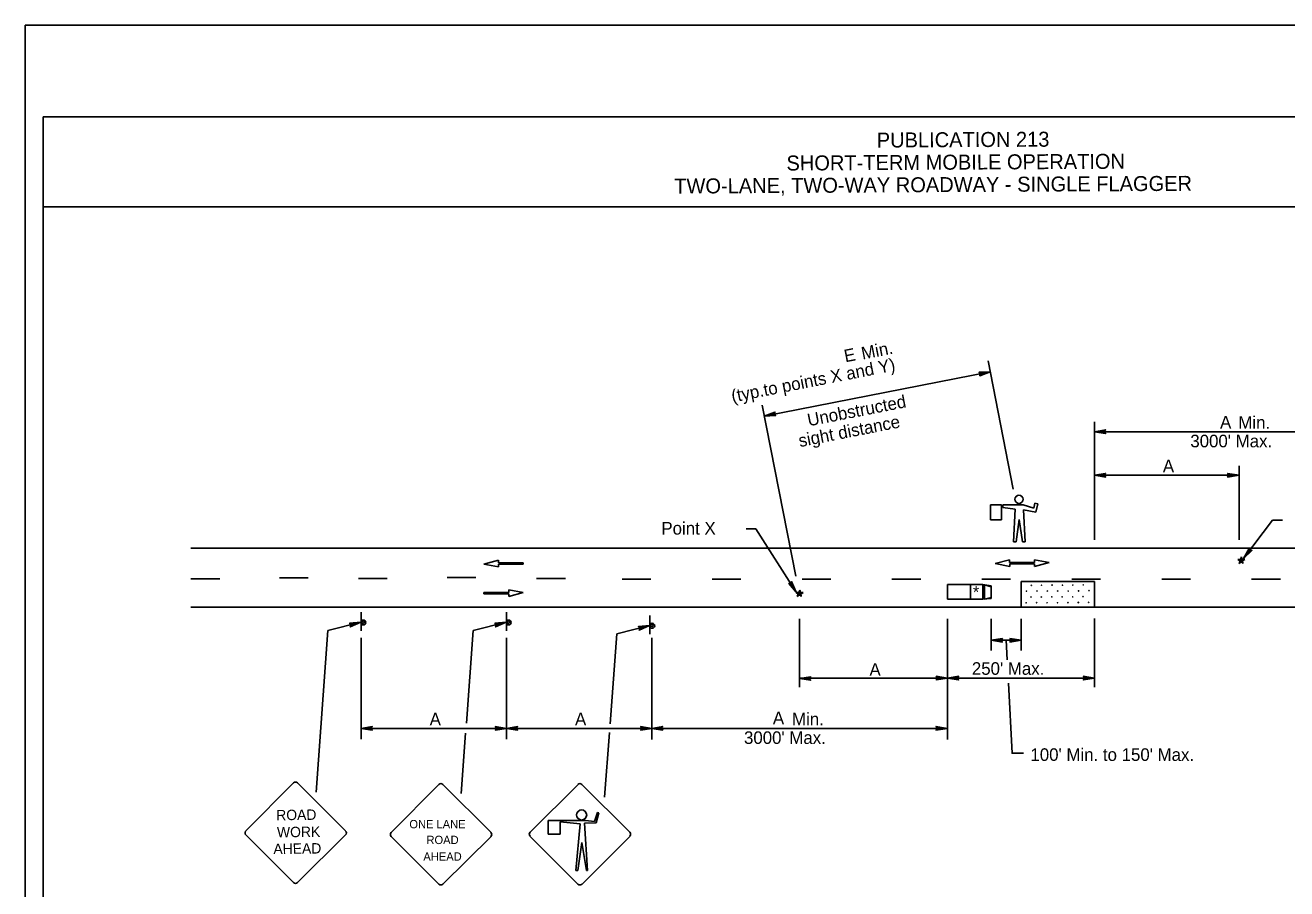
# Model space of a CAD drawing. Extents: x -14145 to -13662, y 30244 to 30661.
# Drawn here: x -13892.17 to -13871.13, y 30462.9 to 30477.31 of the extents above; entities that cross this region are included whole.
import ezdxf

# ---------------------------------------------------------------- set-up
doc = ezdxf.new("R2010")
doc.units = 0
for name, color, linetype in [('1', 7, 'Continuous'), ('10', 7, 'Continuous'), ('2', 7, 'Continuous'), ('4', 7, 'Continuous'), ('61', 7, 'Continuous')]:
    doc.layers.add(name, color=color, linetype=linetype)

msp = doc.modelspace()

# ---------------------------------------------------------------- linework, layer by layer
at = {"layer": '1'}
for p, q in [((-13875.693, 30469.57), (-13876.111, 30471.707)), ((-13876.076, 30471.528), (-13879.846, 30470.789)), ((-13879.322, 30468.116), (-13879.881, 30470.969)), ((-13874.338, 30468.722), (-13874.338, 30470.692)), ((-13869.454, 30470.527), (-13874.338, 30470.527)), ((-13871.926, 30468.722), (-13871.926, 30469.959)), ((-13871.926, 30469.802), (-13874.338, 30469.802)), ((-13875.887, 30469.306), (-13876.075, 30469.306)), ((-13876.075, 30469.306), (-13876.075, 30469.056)), ((-13875.887, 30469.056), (-13875.887, 30469.306)), ((-13875.529, 30469.306), (-13875.869, 30469.306)), ((-13875.869, 30469.306), (-13875.869, 30469.262)), ((-13875.869, 30469.262), (-13875.663, 30469.236)), ((-13875.351, 30469.254), (-13875.529, 30469.306)), ((-13875.333, 30469.334), (-13875.351, 30469.254)), ((-13875.285, 30469.322), (-13875.333, 30469.334)), ((-13875.315, 30469.188), (-13875.285, 30469.322)), ((-13876.075, 30469.056), (-13875.887, 30469.056)), ((-13875.663, 30469.236), (-13875.691, 30468.69)), ((-13875.646, 30468.69), (-13875.592, 30469.064)), ((-13875.592, 30469.064), (-13875.539, 30468.69)), ((-13875.494, 30468.69), (-13875.52, 30469.226)), ((-13875.52, 30469.226), (-13875.315, 30469.188)), ((-13871.85, 30468.415), (-13871.367, 30469.053)), ((-13871.202, 30469.053), (-13871.367, 30469.053)), ((-13880.15, 30468.91), (-13879.985, 30468.91)), ((-13879.315, 30467.854), (-13879.984, 30468.91)), ((-13875.691, 30468.69), (-13875.646, 30468.69)), ((-13875.539, 30468.69), (-13875.494, 30468.69)), ((-13889.41, 30468.586), (-13863.13, 30468.586)), ((-13884.281, 30468.384), (-13884.523, 30468.318)), ((-13884.523, 30468.318), (-13884.279, 30468.272)), ((-13884.281, 30468.339), (-13884.281, 30468.384)), ((-13883.865, 30468.339), (-13884.281, 30468.339)), ((-13884.279, 30468.272), (-13884.279, 30468.317)), ((-13884.279, 30468.317), (-13883.865, 30468.317)), ((-13883.865, 30468.317), (-13883.865, 30468.339)), ((-13875.753, 30468.393), (-13875.994, 30468.327)), ((-13875.994, 30468.327), (-13875.75, 30468.281)), ((-13875.753, 30468.348), (-13875.753, 30468.393)), ((-13875.339, 30468.348), (-13875.753, 30468.348)), ((-13875.75, 30468.326), (-13875.336, 30468.326)), ((-13875.75, 30468.281), (-13875.75, 30468.326)), ((-13875.095, 30468.347), (-13875.339, 30468.393)), ((-13875.339, 30468.393), (-13875.339, 30468.348)), ((-13875.336, 30468.281), (-13875.095, 30468.347)), ((-13875.336, 30468.326), (-13875.336, 30468.281)), ((-13871.915, 30468.372), (-13871.927, 30468.33)), ((-13888.93, 30468.076), (-13889.41, 30468.076)), ((-13887.454, 30468.088), (-13887.934, 30468.088)), ((-13886.134, 30468.082), (-13886.614, 30468.082)), ((-13884.658, 30468.094), (-13885.138, 30468.094)), ((-13883.164, 30468.082), (-13883.644, 30468.082)), ((-13881.736, 30468.07), (-13882.216, 30468.07)), ((-13880.236, 30468.07), (-13880.716, 30468.07)), ((-13878.736, 30468.07), (-13879.216, 30468.07)), ((-13877.236, 30468.07), (-13877.716, 30468.07)), ((-13876.792, 30467.734), (-13876.792, 30467.98)), ((-13876.198, 30467.98), (-13876.792, 30467.98)), ((-13876.408, 30467.734), (-13876.408, 30467.98)), ((-13875.736, 30468.07), (-13876.216, 30468.07)), ((-13876.198, 30467.734), (-13876.198, 30467.98)), ((-13876.198, 30467.98), (-13876.06, 30467.956)), ((-13874.338, 30468.028), (-13875.562, 30468.028)), ((-13875.562, 30467.602), (-13875.562, 30468.028)), ((-13874.236, 30468.07), (-13874.716, 30468.07)), ((-13874.338, 30467.602), (-13874.338, 30468.028)), ((-13872.736, 30468.07), (-13873.216, 30468.07)), ((-13871.236, 30468.07), (-13871.716, 30468.07)), ((-13884.109, 30467.848), (-13884.523, 30467.848)), ((-13884.523, 30467.848), (-13884.523, 30467.826)), ((-13884.523, 30467.826), (-13884.106, 30467.826)), ((-13883.865, 30467.847), (-13884.109, 30467.893)), ((-13884.109, 30467.893), (-13884.109, 30467.848)), ((-13884.106, 30467.781), (-13883.865, 30467.847)), ((-13884.106, 30467.826), (-13884.106, 30467.781)), ((-13879.283, 30467.82), (-13879.295, 30467.778)), ((-13876.174, 30467.974), (-13876.06, 30467.938)), ((-13876.174, 30467.734), (-13876.174, 30467.974)), ((-13876.06, 30467.746), (-13876.06, 30467.956)), ((-13889.41, 30467.602), (-13863.13, 30467.602)), ((-13876.198, 30467.734), (-13876.792, 30467.734)), ((-13876.198, 30467.734), (-13876.06, 30467.746)), ((-13876.174, 30467.734), (-13876.06, 30467.764)), ((-13887.125, 30467.21), (-13886.578, 30467.35)), ((-13886.572, 30467.517), (-13886.572, 30467.205)), ((-13884.701, 30467.21), (-13884.154, 30467.35)), ((-13884.148, 30467.517), (-13884.148, 30467.205)), ((-13881.754, 30467.463), (-13881.754, 30467.151)), ((-13881.754, 30467.463), (-13881.754, 30467.151)), ((-13879.258, 30466.268), (-13879.258, 30467.408)), ((-13876.792, 30465.392), (-13876.792, 30467.408)), ((-13876.06, 30466.879), (-13876.06, 30467.408)), ((-13875.562, 30466.879), (-13875.562, 30467.408)), ((-13874.338, 30466.268), (-13874.338, 30467.414)), ((-13887.323, 30464.513), (-13887.125, 30467.21)), ((-13884.815, 30465.666), (-13884.701, 30467.211)), ((-13882.417, 30465.653), (-13882.307, 30467.157)), ((-13882.307, 30467.156), (-13881.76, 30467.296)), ((-13886.572, 30465.4), (-13886.572, 30467.088)), ((-13884.148, 30465.4), (-13884.148, 30467.088)), ((-13881.724, 30465.392), (-13881.724, 30467.088)), ((-13875.562, 30467.048), (-13876.06, 30467.048)), ((-13876.792, 30466.418), (-13879.258, 30466.418)), ((-13874.338, 30466.418), (-13876.792, 30466.418)), ((-13884.148, 30465.58), (-13886.572, 30465.58)), ((-13884.903, 30464.496), (-13884.829, 30465.502)), ((-13881.724, 30465.58), (-13884.148, 30465.58)), ((-13882.509, 30464.434), (-13882.43, 30465.511)), ((-13876.792, 30465.58), (-13881.724, 30465.58)), ((-13887.698, 30464.671), (-13888.493, 30463.868)), ((-13886.829, 30463.868), (-13887.632, 30464.671)), ((-13885.273, 30464.645), (-13886.068, 30463.842)), ((-13884.404, 30463.842), (-13885.207, 30464.645)), ((-13882.949, 30464.642), (-13883.752, 30463.847)), ((-13882.087, 30463.847), (-13882.889, 30464.642)), ((-13882.087, 30463.847), (-13882.889, 30464.642)), ((-13882.829, 30464.042), (-13883.452, 30464.042)), ((-13883.452, 30464.042), (-13883.452, 30463.817)), ((-13883.249, 30463.817), (-13883.249, 30464.019)), ((-13883.249, 30464.019), (-13882.919, 30463.989)), ((-13882.919, 30463.989), (-13882.987, 30463.209)), ((-13882.844, 30463.997), (-13882.649, 30464.004)), ((-13882.792, 30463.209), (-13882.844, 30463.997)), ((-13882.679, 30464.027), (-13882.829, 30464.042)), ((-13882.627, 30464.177), (-13882.679, 30464.027)), ((-13882.649, 30464.004), (-13882.604, 30464.169)), ((-13882.604, 30464.169), (-13882.627, 30464.177)), ((-13888.493, 30463.802), (-13887.698, 30463.007)), ((-13887.632, 30463.007), (-13886.829, 30463.802)), ((-13886.068, 30463.776), (-13885.273, 30462.981)), ((-13885.207, 30462.981), (-13884.404, 30463.776)), ((-13883.752, 30463.779), (-13882.949, 30462.977)), ((-13883.452, 30463.817), (-13883.249, 30463.817)), ((-13882.889, 30462.977), (-13882.087, 30463.779)), ((-13882.957, 30463.209), (-13882.889, 30463.674)), ((-13882.889, 30463.674), (-13882.814, 30463.209)), ((-13882.987, 30463.209), (-13882.957, 30463.209)), ((-13882.814, 30463.209), (-13882.792, 30463.209))]:
    msp.add_line(p, q, dxfattribs=at)
for points in [[(-13876.257, 30471.515), (-13876.249, 30471.505), (-13876.076, 30471.528), (-13876.257, 30471.515), (-13876.264, 30471.52), (-13876.076, 30471.528), (-13876.245, 30471.487), (-13876.249, 30471.474), (-13876.076, 30471.528), (-13876.252, 30471.461), (-13876.249, 30471.474)], [(-13879.664, 30470.802), (-13879.672, 30470.812), (-13879.845, 30470.789), (-13879.664, 30470.802), (-13879.657, 30470.797), (-13879.845, 30470.789), (-13879.676, 30470.83), (-13879.672, 30470.843), (-13879.845, 30470.789), (-13879.669, 30470.856), (-13879.672, 30470.843)], [(-13874.158, 30470.509), (-13874.164, 30470.521), (-13874.338, 30470.527), (-13874.158, 30470.509), (-13874.152, 30470.497), (-13874.338, 30470.527), (-13874.17, 30470.539), (-13874.164, 30470.551), (-13874.338, 30470.527), (-13874.152, 30470.557), (-13874.164, 30470.551)], [(-13874.158, 30469.784), (-13874.164, 30469.796), (-13874.338, 30469.802), (-13874.158, 30469.784), (-13874.152, 30469.772), (-13874.338, 30469.802), (-13874.17, 30469.814), (-13874.164, 30469.826), (-13874.338, 30469.802), (-13874.152, 30469.832), (-13874.164, 30469.826)], [(-13872.106, 30469.826), (-13872.1, 30469.814), (-13871.926, 30469.802), (-13872.106, 30469.826), (-13872.118, 30469.832), (-13871.926, 30469.802), (-13872.1, 30469.796), (-13872.106, 30469.784), (-13871.926, 30469.802), (-13872.118, 30469.772), (-13872.106, 30469.784)], [(-13871.726, 30468.546), (-13871.739, 30468.542), (-13871.85, 30468.415), (-13871.726, 30468.546), (-13871.713, 30468.549), (-13871.85, 30468.415), (-13871.753, 30468.559), (-13871.764, 30468.567), (-13871.85, 30468.415), (-13871.76, 30468.578), (-13871.764, 30468.567)], [(-13879.394, 30468.016), (-13879.395, 30468.003), (-13879.315, 30467.854), (-13879.394, 30468.016), (-13879.392, 30468.029), (-13879.315, 30467.854), (-13879.416, 30467.995), (-13879.427, 30467.988), (-13879.315, 30467.854), (-13879.436, 30467.996), (-13879.427, 30467.988)], [(-13886.758, 30467.326), (-13886.746, 30467.314), (-13886.578, 30467.35), (-13886.758, 30467.326), (-13886.764, 30467.332), (-13886.578, 30467.35), (-13886.74, 30467.296), (-13886.746, 30467.284), (-13886.578, 30467.35), (-13886.752, 30467.272), (-13886.746, 30467.284)], [(-13884.334, 30467.326), (-13884.322, 30467.314), (-13884.154, 30467.35), (-13884.334, 30467.326), (-13884.34, 30467.332), (-13884.154, 30467.35), (-13884.316, 30467.296), (-13884.322, 30467.284), (-13884.154, 30467.35), (-13884.328, 30467.272), (-13884.322, 30467.284)], [(-13881.94, 30467.272), (-13881.928, 30467.26), (-13881.76, 30467.296), (-13881.94, 30467.272), (-13881.946, 30467.278), (-13881.76, 30467.296), (-13881.922, 30467.242), (-13881.928, 30467.23), (-13881.76, 30467.296), (-13881.934, 30467.218), (-13881.928, 30467.23)], [(-13875.88, 30467.024), (-13875.886, 30467.036), (-13876.06, 30467.048), (-13875.88, 30467.024), (-13875.874, 30467.018), (-13876.06, 30467.048), (-13875.886, 30467.054), (-13875.88, 30467.066), (-13876.06, 30467.048), (-13875.874, 30467.078), (-13875.88, 30467.066)], [(-13875.794, 30466.723), (-13875.811, 30467.048)], [(-13875.742, 30467.072), (-13875.736, 30467.054), (-13875.562, 30467.048), (-13875.742, 30467.072), (-13875.748, 30467.078), (-13875.562, 30467.048), (-13875.736, 30467.042), (-13875.742, 30467.024), (-13875.562, 30467.048), (-13875.748, 30467.018), (-13875.742, 30467.024)], [(-13879.078, 30466.388), (-13879.084, 30466.4), (-13879.258, 30466.412), (-13879.078, 30466.388), (-13879.072, 30466.382), (-13879.258, 30466.412), (-13879.084, 30466.418), (-13879.078, 30466.43), (-13879.258, 30466.412), (-13879.072, 30466.442), (-13879.078, 30466.43)], [(-13876.972, 30466.442), (-13876.966, 30466.424), (-13876.792, 30466.418), (-13876.972, 30466.442), (-13876.978, 30466.448), (-13876.792, 30466.418), (-13876.966, 30466.412), (-13876.972, 30466.394), (-13876.792, 30466.418), (-13876.978, 30466.388), (-13876.972, 30466.394)], [(-13876.612, 30466.394), (-13876.618, 30466.406), (-13876.792, 30466.418), (-13876.612, 30466.394), (-13876.606, 30466.388), (-13876.792, 30466.418), (-13876.618, 30466.424), (-13876.612, 30466.436), (-13876.792, 30466.418), (-13876.606, 30466.448), (-13876.612, 30466.436)], [(-13875.52, 30465.164), (-13875.712, 30465.164), (-13875.774, 30466.336)], [(-13874.518, 30466.442), (-13874.512, 30466.424), (-13874.338, 30466.418), (-13874.518, 30466.442), (-13874.524, 30466.448), (-13874.338, 30466.418), (-13874.512, 30466.412), (-13874.518, 30466.394), (-13874.338, 30466.418), (-13874.524, 30466.388), (-13874.518, 30466.394)], [(-13886.392, 30465.562), (-13886.398, 30465.574), (-13886.572, 30465.58), (-13886.392, 30465.562), (-13886.386, 30465.55), (-13886.572, 30465.58), (-13886.398, 30465.592), (-13886.392, 30465.604), (-13886.572, 30465.58), (-13886.386, 30465.61), (-13886.392, 30465.604)], [(-13884.328, 30465.604), (-13884.316, 30465.586), (-13884.148, 30465.58), (-13884.328, 30465.604), (-13884.334, 30465.61), (-13884.148, 30465.58), (-13884.316, 30465.568), (-13884.328, 30465.556), (-13884.148, 30465.58), (-13884.334, 30465.55), (-13884.328, 30465.556)], [(-13883.968, 30465.562), (-13883.974, 30465.574), (-13884.148, 30465.58), (-13883.968, 30465.562), (-13883.962, 30465.55), (-13884.148, 30465.58), (-13883.974, 30465.592), (-13883.968, 30465.604), (-13884.148, 30465.58), (-13883.962, 30465.61), (-13883.968, 30465.604)], [(-13881.904, 30465.604), (-13881.892, 30465.586), (-13881.724, 30465.58), (-13881.904, 30465.604), (-13881.91, 30465.61), (-13881.724, 30465.58), (-13881.892, 30465.568), (-13881.904, 30465.556), (-13881.724, 30465.58), (-13881.91, 30465.55), (-13881.904, 30465.556)], [(-13881.544, 30465.562), (-13881.55, 30465.574), (-13881.724, 30465.58), (-13881.544, 30465.562), (-13881.538, 30465.55), (-13881.724, 30465.58), (-13881.556, 30465.592), (-13881.55, 30465.604), (-13881.724, 30465.58), (-13881.538, 30465.61), (-13881.55, 30465.604)], [(-13876.972, 30465.604), (-13876.966, 30465.592), (-13876.792, 30465.58), (-13876.972, 30465.604), (-13876.984, 30465.61), (-13876.792, 30465.58), (-13876.966, 30465.574), (-13876.972, 30465.562), (-13876.792, 30465.58), (-13876.984, 30465.55), (-13876.972, 30465.562)]]:
    msp.add_lwpolyline(points, dxfattribs=at)
for centre, radius in [((-13875.597, 30469.4), 0.0672), ((-13875.472, 30467.869), 0.00272), ((-13875.397, 30467.771), 0.00272), ((-13875.392, 30467.967), 0.00272), ((-13875.297, 30467.871), 0.00272), ((-13875.226, 30467.771), 0.00272), ((-13875.219, 30467.968), 0.00272), ((-13875.125, 30467.869), 0.00272), ((-13875.049, 30467.772), 0.00272), ((-13875.045, 30467.969), 0.00272), ((-13874.95, 30467.871), 0.00272), ((-13874.876, 30467.772), 0.00272), ((-13874.871, 30467.968), 0.00272), ((-13874.776, 30467.87), 0.00272), ((-13874.701, 30467.773), 0.00272), ((-13874.699, 30467.97), 0.00272), ((-13874.604, 30467.875), 0.00272), ((-13874.602, 30467.872), 0.00272), ((-13874.53, 30467.777), 0.00272), ((-13874.524, 30467.973), 0.00272), ((-13874.429, 30467.877), 0.00272), ((-13875.477, 30467.674), 0.00272), ((-13875.302, 30467.675), 0.00272), ((-13875.129, 30467.674), 0.00272), ((-13874.955, 30467.676), 0.00272), ((-13874.781, 30467.677), 0.00272), ((-13874.609, 30467.68), 0.00272), ((-13874.608, 30467.677), 0.00272), ((-13874.435, 30467.681), 0.00272), ((-13886.533, 30467.345), 0.0408), ((-13884.109, 30467.345), 0.0408), ((-13881.715, 30467.291), 0.0408), ((-13882.892, 30464.135), 0.0844)]:
    msp.add_circle(centre, radius, dxfattribs=at)
for centre, radius, start, end in [((-13886.538, 30467.353), 0.0214, 189.521, 184.2501), ((-13884.114, 30467.353), 0.0214, 189.521, 184.2501), ((-13881.72, 30467.299), 0.0214, 189.521, 184.2501), ((-13887.666, 30464.638), 0.0465, 45, 135), ((-13885.241, 30464.612), 0.0465, 45, 135), ((-13882.921, 30464.613), 0.0465, 45, 135), ((-13888.461, 30463.835), 0.0465, 135, 225), ((-13886.863, 30463.835), 0.0465, 315, 45), ((-13886.036, 30463.81), 0.0465, 135, 225), ((-13884.438, 30463.809), 0.0465, 315, 45), ((-13883.72, 30463.814), 0.0465, 135, 225), ((-13882.122, 30463.814), 0.0465, 315, 45), ((-13887.666, 30463.04), 0.0465, 225, 315), ((-13885.241, 30463.014), 0.0465, 225, 315), ((-13882.921, 30463.015), 0.0465, 225, 315)]:
    msp.add_arc(centre, radius, start, end, dxfattribs=at)
at = {"layer": '10'}
for p, q in [((-13891.874, 30475.777), (-13860.422, 30475.777)), ((-13891.874, 30453.207), (-13891.874, 30475.777)), ((-13891.874, 30474.277), (-13860.422, 30474.277))]:
    msp.add_line(p, q, dxfattribs=at)
at = {"layer": '2'}
for p, q in [((-13871.903, 30468.396), (-13871.885, 30468.438)), ((-13871.885, 30468.438), (-13871.873, 30468.396)), ((-13871.915, 30468.372), (-13871.945, 30468.396)), ((-13871.945, 30468.396), (-13871.903, 30468.396)), ((-13871.927, 30468.33), (-13871.915, 30468.372)), ((-13871.891, 30468.36), (-13871.927, 30468.33)), ((-13871.861, 30468.33), (-13871.891, 30468.36)), ((-13871.873, 30468.396), (-13871.831, 30468.396)), ((-13871.831, 30468.396), (-13871.867, 30468.372)), ((-13871.867, 30468.372), (-13871.861, 30468.33)), ((-13879.283, 30467.82), (-13879.313, 30467.844)), ((-13879.313, 30467.844), (-13879.271, 30467.844)), ((-13879.295, 30467.778), (-13879.283, 30467.82)), ((-13879.259, 30467.808), (-13879.295, 30467.778)), ((-13879.271, 30467.844), (-13879.253, 30467.886)), ((-13879.229, 30467.778), (-13879.259, 30467.808)), ((-13879.253, 30467.886), (-13879.241, 30467.844)), ((-13879.241, 30467.844), (-13879.199, 30467.844)), ((-13879.199, 30467.844), (-13879.235, 30467.82)), ((-13879.235, 30467.82), (-13879.229, 30467.778))]:
    msp.add_line(p, q, dxfattribs=at)
for points in [[(-13871.891, 30468.42), (-13871.897, 30468.39), (-13871.933, 30468.39), (-13871.909, 30468.378), (-13871.921, 30468.342), (-13871.891, 30468.36), (-13871.861, 30468.342), (-13871.873, 30468.378), (-13871.843, 30468.39), (-13871.879, 30468.39), (-13871.885, 30468.426), (-13871.891, 30468.384), (-13871.921, 30468.39), (-13871.903, 30468.378), (-13871.915, 30468.348), (-13871.891, 30468.366), (-13871.867, 30468.348), (-13871.879, 30468.378), (-13871.855, 30468.39), (-13871.879, 30468.39), (-13871.885, 30468.408), (-13871.891, 30468.384), (-13871.909, 30468.384), (-13871.897, 30468.378), (-13871.903, 30468.36), (-13871.891, 30468.372), (-13871.879, 30468.36), (-13871.879, 30468.378), (-13871.861, 30468.384), (-13871.879, 30468.384), (-13871.885, 30468.39), (-13871.885, 30468.378), (-13871.897, 30468.378), (-13871.897, 30468.378), (-13871.897, 30468.366), (-13871.891, 30468.372), (-13871.879, 30468.366), (-13871.885, 30468.378), (-13871.873, 30468.378), (-13871.885, 30468.378), (-13871.885, 30468.378), (-13871.891, 30468.378), (-13871.891, 30468.378), (-13871.885, 30468.372), (-13871.891, 30468.378), (-13871.891, 30468.378), (-13871.891, 30468.378), (-13871.891, 30468.378)], [(-13879.259, 30467.868), (-13879.265, 30467.838), (-13879.301, 30467.838), (-13879.277, 30467.826), (-13879.289, 30467.79), (-13879.259, 30467.808), (-13879.229, 30467.79), (-13879.241, 30467.826), (-13879.211, 30467.838), (-13879.247, 30467.838), (-13879.253, 30467.874), (-13879.259, 30467.832), (-13879.289, 30467.838), (-13879.271, 30467.826), (-13879.283, 30467.796), (-13879.259, 30467.814), (-13879.235, 30467.796), (-13879.247, 30467.826), (-13879.223, 30467.838), (-13879.247, 30467.838), (-13879.253, 30467.856), (-13879.259, 30467.832), (-13879.277, 30467.832), (-13879.265, 30467.826), (-13879.271, 30467.808), (-13879.259, 30467.82), (-13879.247, 30467.808), (-13879.247, 30467.826), (-13879.229, 30467.832), (-13879.247, 30467.832), (-13879.253, 30467.838), (-13879.253, 30467.826), (-13879.265, 30467.826), (-13879.265, 30467.826), (-13879.265, 30467.814), (-13879.259, 30467.82), (-13879.247, 30467.814), (-13879.253, 30467.826), (-13879.241, 30467.826), (-13879.253, 30467.826), (-13879.253, 30467.826), (-13879.259, 30467.826), (-13879.259, 30467.826), (-13879.253, 30467.82), (-13879.259, 30467.826), (-13879.259, 30467.826), (-13879.259, 30467.826), (-13879.259, 30467.826)]]:
    msp.add_lwpolyline(points, dxfattribs=at)
at = {"layer": '61'}
msp.add_lwpolyline([(-13892.174, 30477.307), (-13859.174, 30477.307), (-13859.174, 30451.807), (-13892.174, 30451.807)], close=True, dxfattribs=at)

# ---------------------------------------------------------------- texts
at = {"layer": '1'}
for s, height, rotation, p in [('*', 0.198, 0.7233, (-13876.363, 30467.753)), ('ROAD', 0.1735, 0.7566, (-13887.986, 30464.046)), ('WORK', 0.1733, 0.7588, (-13887.973, 30463.761)), ('AHEAD', 0.1735, 0.7481, (-13888.033, 30463.483))]:
    msp.add_text(s, height=height, rotation=rotation, dxfattribs=at).set_placement(p)
for s, height, p in [('ONE LANE', 0.1386, (-13885.766, 30463.913)), ('ROAD', 0.1389, (-13885.481, 30463.65)), ('AHEAD', 0.139, (-13885.533, 30463.373))]:
    msp.add_text(s, height=height, dxfattribs=at).set_placement(p)
at = {"layer": '2'}
for s, p in [('Min.', (-13878.206, 30471.729)), ('E', (-13878.493, 30471.684)), ('(typ.to points X and Y)', (-13880.374, 30471.015)), ('Unobstructed', (-13879.105, 30470.616)), ('sight distance', (-13879.252, 30470.27))]:
    msp.add_text(s, height=0.21, rotation=11.0819, dxfattribs=at).set_placement(p)
for s, p in [('A', (-13872.243, 30470.581)), ('Min.', (-13871.938, 30470.576)), ("3000' Max.", (-13872.739, 30470.267)), ('A', (-13873.197, 30469.851)), ('Point X', (-13881.562, 30468.812)), ('A', (-13878.091, 30466.457)), ("250' Max.", (-13876.383, 30466.473)), ('A', (-13885.427, 30465.631)), ('A', (-13883.003, 30465.631)), ('A', (-13879.702, 30465.649)), ('Min.', (-13879.383, 30465.629)), ("3000' Max.", (-13880.184, 30465.32)), ("100' Min. to 150' Max.", (-13875.406, 30465.037))]:
    msp.add_text(s, height=0.21, dxfattribs=at).set_placement(p)
at = {"layer": '4'}
for s, p in [('PUBLICATION 213', (-13877.969, 30475.266)), ('SHORT-TERM MOBILE OPERATION', (-13879.475, 30474.883)), ('TWO-LANE, TWO-WAY ROADWAY - SINGLE FLAGGER', (-13881.347, 30474.499))]:
    msp.add_text(s, height=0.25, rotation=0.31, dxfattribs=at).set_placement(p)

doc.saveas('drawing.dxf')
